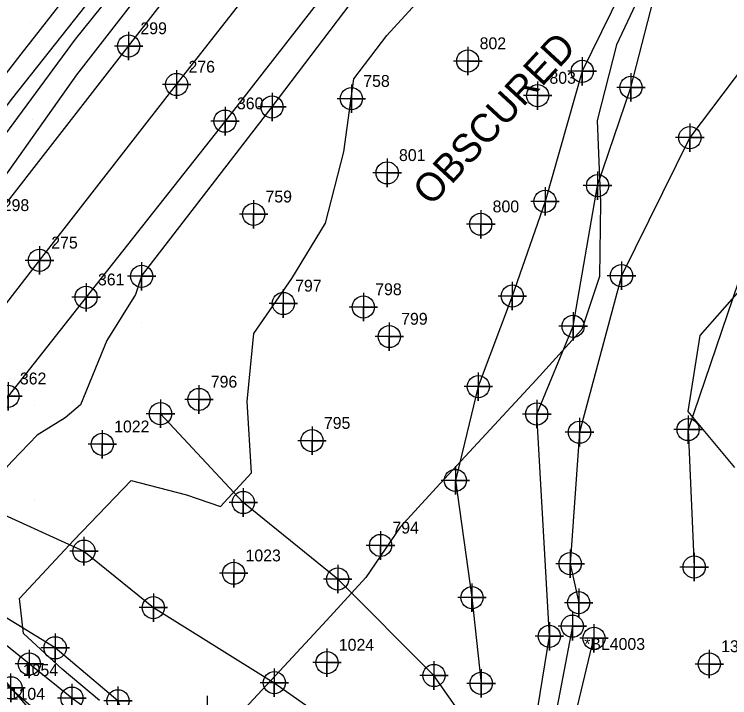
# Model space of a CAD drawing. Extents: x 1497074 to 1501343, y 481943 to 486114.
# Drawn here: x 1498779.1 to 1498929.9, y 484965.4 to 485109.5 of the extents above; entities that cross this region are included whole.
import ezdxf

# ---------------------------------------------------------------- set-up
doc = ezdxf.new("R2010")
doc.units = 0
for name, color, linetype in [('Exist DTM Breakline', 7, 'Continuous'), ('Exist DTM Breakline Cogo Point CELL', 7, 'Continuous'), ('Exist DTM Breakline Underwater Cogo Number', 7, 'Continuous'), ('Exist DTM Crownline', 7, 'Continuous'), ('Exist DTM Crownline Cogo Number', 7, 'Continuous'), ('Exist DTM Crownline Cogo Point CELL', 7, 'Continuous'), ('Exist DTM Drainline', 7, 'Continuous'), ('Exist DTM Drainline Cogo Comment', 7, 'Continuous'), ('Exist DTM Drainline Cogo Point CELL', 7, 'Continuous'), ('Exist DTM Regular Point CELL', 7, 'Continuous'), ('Exist DTM Regular Point Cogo Number', 7, 'Continuous'), ('Exist Hydro Stream or Body of Water', 7, 'Continuous'), ('Exist Hydro Stream or Body of Water Cogo Number', 7, 'Continuous'), ('Exist Hydro Stream or Body of Water Cogo Point CELL', 7, 'Continuous'), ('Exist Roads EOP', 7, 'Continuous'), ('Exist Roads EOP Cogo Number', 7, 'Continuous'), ('Exist Roads EOP Cogo Point CELL', 7, 'Continuous'), ('PH Exist DTM Boundary', 7, 'Continuous'), ('PH Exist DTM Breakline', 7, 'Continuous'), ('PH Exist DTM Obscure Area', 7, 'Continuous'), ('PH Exist DTM Obscure Area Text', 7, 'Continuous'), ('PH Exist DTM Point', 7, 'Continuous')]:
    doc.layers.add(name, color=color, linetype=linetype)

msp = doc.modelspace()

# ---------------------------------------------------------------- linework, layer by layer
at = {"layer": 'Exist DTM Breakline'}
for points in [[(1498805.95, 485054.25), (1498833.45, 485089.98), (1498860.79, 485126.09), (1498887.46, 485159.9), (1498914.16, 485195.14), (1498935.01, 485223.58), (1498950.21, 485241.65)], [(1498963.58, 485154.61), (1498950.43, 485151.68), (1498933.68, 485147.06), (1498922.77, 485137.59), (1498906.95, 485114.19), (1498898.82, 485097.51), (1498890.98, 485070.05), (1498884.07, 485050.09), (1498876.91, 485030.97), (1498872.08, 485011.19)], [(1498891.9, 484978.31), (1498889.24, 485025.19), (1498896.9, 485043.7), (1498902.05, 485073.39), (1498909.09, 485094.11), (1498914.43, 485114.93), (1498921.86, 485126.97), (1498937, 485141.32), (1498954.93, 485147.67), (1498969.97, 485147.43)], [(1498999.68, 485104.8), (1498976.97, 485110), (1498959.54, 485112.86), (1498942.37, 485111.16), (1498921.51, 485083.5), (1498907.1, 485054.37), (1498898.24, 485021.36), (1498896.28, 484993.61), (1498898.08, 484985.39)], [(1498969.44, 485104.51), (1498948.52, 485082.03), (1498932.91, 485056.44), (1498921.14, 485021.92), (1498922.42, 484992.91)], [(1498886.17, 484945.87), (1498882.87, 484948.24), (1498867.57, 484970.04), (1498847.28, 484990.38), (1498827.38, 485006.53), (1498809.93, 485025.26)], [(1498872.08, 485011.19), (1498875.57, 484986.46), (1498877.52, 484968.37)], [(1498848.29, 484918.89), (1498845.04, 484921.7), (1498840.43, 484924.27), (1498836.93, 484932.71), (1498831.61, 484940.16), (1498825.71, 484945.62), (1498813.99, 484951.95), (1498810.05, 484953.43), (1498804.82, 484955.73), (1498800.95, 484964.7), (1498787.72, 484975.87), (1498775.66, 484983.28), (1498764.52, 484991.6), (1498761.62, 485000.66), (1498761.1, 485004.19), (1498764.01, 485009), (1498765.64, 485007.52), (1498768.65, 485008.02)], [(1498775.21, 485004.72), (1498793.79, 484996.26), (1498808.42, 484984.36), (1498833.91, 484968.52), (1498856.98, 484952.27), (1498870.26, 484939.1), (1498876.95, 484932.87)], [(1498800.01, 484958.89), (1498791.25, 484965.26), (1498782.28, 484972.47), (1498771.97, 484980.76)], [(1498890, 484942.31), (1498886.17, 484945.87), (1498887.51, 484951.1), (1498891.9, 484978.31)], [(1498890, 484942.31), (1498893.99, 484947.35), (1498901.29, 484977.88)]]:
    msp.add_lwpolyline(points, dxfattribs=at)
at = {"layer": 'Exist DTM Breakline Cogo Point CELL'}
for points in [[(1498898.82, 485100.51), (1498898.82, 485094.51), (1498898.82, 485097.51), (1498901.82, 485097.51), (1498895.82, 485097.51)], [(1498909.09, 485097.11), (1498909.09, 485091.11), (1498909.09, 485094.11), (1498912.09, 485094.11), (1498906.09, 485094.11)], [(1498833.45, 485092.98), (1498833.45, 485086.98), (1498833.45, 485089.98), (1498836.45, 485089.98), (1498830.45, 485089.98)], [(1498921.51, 485086.5), (1498921.51, 485080.5), (1498921.51, 485083.5), (1498924.51, 485083.5), (1498918.51, 485083.5)], [(1498902.05, 485076.39), (1498902.05, 485070.39), (1498902.05, 485073.39), (1498905.05, 485073.39), (1498899.05, 485073.39)], [(1498890.98, 485073.05), (1498890.98, 485067.05), (1498890.98, 485070.05), (1498893.98, 485070.05), (1498887.98, 485070.05)], [(1498805.95, 485057.25), (1498805.95, 485051.25), (1498805.95, 485054.25), (1498808.95, 485054.25), (1498802.95, 485054.25)], [(1498907.1, 485057.37), (1498907.1, 485051.37), (1498907.1, 485054.37), (1498910.1, 485054.37), (1498904.1, 485054.37)], [(1498884.07, 485053.09), (1498884.07, 485047.09), (1498884.07, 485050.09), (1498887.07, 485050.09), (1498881.07, 485050.09)], [(1498896.9, 485046.7), (1498896.9, 485040.7), (1498896.9, 485043.7), (1498899.9, 485043.7), (1498893.9, 485043.7)], [(1498876.91, 485033.97), (1498876.91, 485027.97), (1498876.91, 485030.97), (1498879.91, 485030.97), (1498873.91, 485030.97)], [(1498809.93, 485028.26), (1498809.93, 485022.26), (1498809.93, 485025.26), (1498812.93, 485025.26), (1498806.93, 485025.26)], [(1498889.24, 485028.19), (1498889.24, 485022.19), (1498889.24, 485025.19), (1498892.24, 485025.19), (1498886.24, 485025.19)], [(1498898.24, 485024.36), (1498898.24, 485018.36), (1498898.24, 485021.36), (1498901.24, 485021.36), (1498895.24, 485021.36)], [(1498921.14, 485024.92), (1498921.14, 485018.92), (1498921.14, 485021.92), (1498924.14, 485021.92), (1498918.14, 485021.92)], [(1498872.08, 485014.19), (1498872.08, 485008.19), (1498872.08, 485011.19), (1498875.08, 485011.19), (1498869.08, 485011.19)], [(1498827.38, 485009.53), (1498827.38, 485003.53), (1498827.38, 485006.53), (1498830.38, 485006.53), (1498824.38, 485006.53)], [(1498793.79, 484999.26), (1498793.79, 484993.26), (1498793.79, 484996.26), (1498796.79, 484996.26), (1498790.79, 484996.26)], [(1498896.28, 484996.61), (1498896.28, 484990.61), (1498896.28, 484993.61), (1498899.28, 484993.61), (1498893.28, 484993.61)], [(1498922.42, 484995.91), (1498922.42, 484989.91), (1498922.42, 484992.91), (1498925.42, 484992.91), (1498919.42, 484992.91)], [(1498847.28, 484993.38), (1498847.28, 484987.38), (1498847.28, 484990.38), (1498850.28, 484990.38), (1498844.28, 484990.38)], [(1498875.57, 484989.46), (1498875.57, 484983.46), (1498875.57, 484986.46), (1498878.57, 484986.46), (1498872.57, 484986.46)], [(1498808.42, 484987.36), (1498808.42, 484981.36), (1498808.42, 484984.36), (1498811.42, 484984.36), (1498805.42, 484984.36)], [(1498898.08, 484988.39), (1498898.08, 484982.39), (1498898.08, 484985.39), (1498901.08, 484985.39), (1498895.08, 484985.39)], [(1498891.9, 484981.31), (1498891.9, 484975.31), (1498891.9, 484978.31), (1498894.9, 484978.31), (1498888.9, 484978.31)], [(1498901.29, 484980.88), (1498901.29, 484974.88), (1498901.29, 484977.88), (1498904.29, 484977.88), (1498898.29, 484977.88)], [(1498787.72, 484978.87), (1498787.72, 484972.87), (1498787.72, 484975.87), (1498790.72, 484975.87), (1498784.72, 484975.87)], [(1498782.28, 484975.47), (1498782.28, 484969.47), (1498782.28, 484972.47), (1498785.28, 484972.47), (1498779.28, 484972.47)], [(1498867.57, 484973.04), (1498867.57, 484967.04), (1498867.57, 484970.04), (1498870.57, 484970.04), (1498864.57, 484970.04)], [(1498833.91, 484971.52), (1498833.91, 484965.52), (1498833.91, 484968.52), (1498836.91, 484968.52), (1498830.91, 484968.52)], [(1498877.52, 484971.37), (1498877.52, 484965.37), (1498877.52, 484968.37), (1498880.52, 484968.37), (1498874.52, 484968.37)], [(1498791.25, 484968.26), (1498791.25, 484962.26), (1498791.25, 484965.26), (1498794.25, 484965.26), (1498788.25, 484965.26)], [(1498800.95, 484967.7), (1498800.95, 484961.7), (1498800.95, 484964.7), (1498803.95, 484964.7), (1498797.95, 484964.7)], [(1498819.73, 484965.72), (1498819.73, 484959.72), (1498819.73, 484962.72), (1498822.73, 484962.72), (1498816.73, 484962.72)]]:
    msp.add_lwpolyline(points, dxfattribs=at)
for centre in [(1498898.82, 485097.51), (1498909.09, 485094.11), (1498833.45, 485089.98), (1498921.51, 485083.5), (1498902.05, 485073.39), (1498890.98, 485070.05), (1498907.1, 485054.37), (1498805.95, 485054.25), (1498884.07, 485050.09), (1498896.9, 485043.7), (1498876.91, 485030.97), (1498809.93, 485025.26), (1498889.24, 485025.19), (1498898.24, 485021.36), (1498921.14, 485021.92), (1498872.08, 485011.19), (1498827.38, 485006.53), (1498793.79, 484996.26), (1498896.28, 484993.61), (1498922.42, 484992.91), (1498847.28, 484990.38), (1498875.57, 484986.46), (1498898.08, 484985.39), (1498808.42, 484984.36), (1498891.9, 484978.31), (1498901.29, 484977.88), (1498787.72, 484975.87), (1498782.28, 484972.47), (1498867.57, 484970.04), (1498833.91, 484968.52), (1498877.52, 484968.37), (1498791.25, 484965.26), (1498800.95, 484964.7)]:
    msp.add_circle(centre, 2.34, dxfattribs=at)
at = {"layer": 'Exist DTM Crownline'}
msp.add_lwpolyline([(1498753.92, 485018.83), (1498767.97, 485036.35), (1498784.41, 485057.61), (1498813.33, 485094.71), (1498845.11, 485135.39), (1498876.05, 485175.22), (1498907.7, 485215.72), (1498939.87, 485257.15), (1498970.73, 485296.32), (1499001.6, 485335.5), (1499032.55, 485374.36), (1499053.88, 485400.5), (1499073.91, 485423.48), (1499090.49, 485441.64), (1499112.37, 485464.57), (1499148.43, 485501.47), (1499184.54, 485537.77), (1499215.93, 485569.25), (1499248.51, 485602.52), (1499285.02, 485638.96), (1499320.99, 485674.8), (1499344.91, 485698.57), (1499374.04, 485727.35), (1499398.21, 485750.96)], dxfattribs=at)
at = {"layer": 'Exist DTM Crownline Cogo Point CELL'}
for points in [[(1498813.33, 485097.71), (1498813.33, 485091.71), (1498813.33, 485094.71), (1498816.33, 485094.71), (1498810.33, 485094.71)], [(1498784.41, 485060.61), (1498784.41, 485054.61), (1498784.41, 485057.61), (1498787.41, 485057.61), (1498781.41, 485057.61)]]:
    msp.add_lwpolyline(points, dxfattribs=at)
for centre in [(1498813.33, 485094.71), (1498784.41, 485057.61)]:
    msp.add_circle(centre, 2.34, dxfattribs=at)
at = {"layer": 'Exist DTM Drainline'}
msp.add_lwpolyline([(1498896.74, 484980.44), (1498890.78, 484949.15), (1498888.83, 484945.44)], dxfattribs=at)
at = {"layer": 'Exist DTM Drainline Cogo Point CELL'}
msp.add_lwpolyline([(1498896.74, 484983.44), (1498896.74, 484977.44), (1498896.74, 484980.44), (1498899.74, 484980.44), (1498893.74, 484980.44)], dxfattribs=at)
msp.add_circle((1498896.74, 484980.44), 2.34, dxfattribs=at)
at = {"layer": 'Exist DTM Regular Point CELL'}
for points in [[(1498874.7, 485102.66), (1498874.7, 485096.66), (1498874.7, 485099.66), (1498877.7, 485099.66), (1498871.7, 485099.66)], [(1498850.17, 485094.71), (1498850.17, 485088.71), (1498850.17, 485091.71), (1498853.17, 485091.71), (1498847.17, 485091.71)], [(1498889.41, 485095.37), (1498889.41, 485089.37), (1498889.41, 485092.37), (1498892.41, 485092.37), (1498886.41, 485092.37)], [(1498857.7, 485079.07), (1498857.7, 485073.07), (1498857.7, 485076.07), (1498860.7, 485076.07), (1498854.7, 485076.07)], [(1498829.56, 485070.33), (1498829.56, 485064.33), (1498829.56, 485067.33), (1498832.56, 485067.33), (1498826.56, 485067.33)], [(1498877.44, 485068.24), (1498877.44, 485062.24), (1498877.44, 485065.24), (1498880.44, 485065.24), (1498874.44, 485065.24)], [(1498835.81, 485051.52), (1498835.81, 485045.52), (1498835.81, 485048.52), (1498838.81, 485048.52), (1498832.81, 485048.52)], [(1498852.69, 485050.77), (1498852.69, 485044.77), (1498852.69, 485047.77), (1498855.69, 485047.77), (1498849.69, 485047.77)], [(1498858.16, 485044.54), (1498858.16, 485038.54), (1498858.16, 485041.54), (1498861.16, 485041.54), (1498855.16, 485041.54)], [(1498818.03, 485031.27), (1498818.03, 485025.27), (1498818.03, 485028.27), (1498821.03, 485028.27), (1498815.03, 485028.27)], [(1498841.87, 485022.57), (1498841.87, 485016.57), (1498841.87, 485019.57), (1498844.87, 485019.57), (1498838.87, 485019.57)], [(1498797.66, 485021.81), (1498797.66, 485015.81), (1498797.66, 485018.81), (1498800.66, 485018.81), (1498794.66, 485018.81)], [(1498856.31, 485000.47), (1498856.31, 484994.47), (1498856.31, 484997.47), (1498859.31, 484997.47), (1498853.31, 484997.47)], [(1498825.36, 484994.61), (1498825.36, 484988.61), (1498825.36, 484991.61), (1498828.36, 484991.61), (1498822.36, 484991.61)], [(1498845.02, 484975.75), (1498845.02, 484969.75), (1498845.02, 484972.75), (1498848.02, 484972.75), (1498842.02, 484972.75)], [(1498925.6, 484975.46), (1498925.6, 484969.46), (1498925.6, 484972.46), (1498928.6, 484972.46), (1498922.6, 484972.46)]]:
    msp.add_lwpolyline(points, dxfattribs=at)
for centre in [(1498874.7, 485099.66), (1498889.41, 485092.37), (1498850.17, 485091.71), (1498857.7, 485076.07), (1498829.56, 485067.33), (1498877.44, 485065.24), (1498835.81, 485048.52), (1498852.69, 485047.77), (1498858.16, 485041.54), (1498818.03, 485028.27), (1498797.66, 485018.81), (1498841.87, 485019.57), (1498856.31, 484997.47), (1498825.36, 484991.61), (1498845.02, 484972.75), (1498925.6, 484972.46)]:
    msp.add_circle(centre, 2.34, dxfattribs=at)
at = {"layer": 'Exist Hydro Stream or Body of Water'}
msp.add_lwpolyline([(1498752.44, 484994.87), (1498757.91, 484987.33), (1498768.39, 484979.37), (1498778.41, 484967.43), (1498786.59, 484957.96), (1498794.74, 484956.31), (1498800.32, 484956.39), (1498808.7, 484950.71), (1498819.06, 484944.96), (1498828.44, 484936.12), (1498833.88, 484929.92), (1498837.65, 484922.31), (1498844.31, 484916.7), (1498846.68, 484914.59)], dxfattribs=at)
at = {"layer": 'Exist Hydro Stream or Body of Water Cogo Point CELL'}
msp.add_lwpolyline([(1498775.41, 484967.43), (1498781.41, 484967.43), (1498778.41, 484967.43), (1498778.41, 484964.43), (1498778.41, 484970.43)], dxfattribs=at)
msp.add_circle((1498778.41, 484967.43), 2.34, dxfattribs=at)
at = {"layer": 'Exist Roads EOP'}
for points in [[(1498744.68, 485026.11), (1498757.92, 485043.98), (1498774.18, 485065.51), (1498803.2, 485102.82), (1498835.11, 485143.9), (1498866.39, 485184.06), (1498897.92, 485224.48), (1498930.45, 485265.81), (1498960.65, 485304.75), (1498991.78, 485343.69), (1499023.06, 485383.27), (1499044.83, 485409.1), (1499064.02, 485432.02), (1499081.8, 485451.06), (1499098.44, 485468.79), (1499108.29, 485478.99), (1499123.4, 485494.87), (1499138.72, 485510.78), (1499164.22, 485538.41), (1499168.24, 485544.59), (1499172.31, 485548.88)], [(1499157.4, 485492.59), (1499121.26, 485455.44), (1499103.51, 485436.37), (1499090.83, 485422.86), (1499076.19, 485406.52), (1499058.81, 485386.53), (1499043.51, 485368.33), (1499011.4, 485327.87), (1498980.6, 485289.07), (1498949.57, 485249.28), (1498917.76, 485208.17), (1498886.39, 485167.84), (1498854.95, 485127.37), (1498823.54, 485086.98), (1498794.25, 485049.83), (1498777.79, 485028.94), (1498763.43, 485011.14)]]:
    msp.add_lwpolyline(points, dxfattribs=at)
at = {"layer": 'Exist Roads EOP Cogo Point CELL'}
for points in [[(1498803.2, 485105.82), (1498803.2, 485099.82), (1498803.2, 485102.82), (1498806.2, 485102.82), (1498800.2, 485102.82)], [(1498823.54, 485089.98), (1498823.54, 485083.98), (1498823.54, 485086.98), (1498826.54, 485086.98), (1498820.54, 485086.98)], [(1498794.25, 485052.83), (1498794.25, 485046.83), (1498794.25, 485049.83), (1498797.25, 485049.83), (1498791.25, 485049.83)], [(1498777.79, 485031.94), (1498777.79, 485025.94), (1498777.79, 485028.94), (1498780.79, 485028.94), (1498774.79, 485028.94)]]:
    msp.add_lwpolyline(points, dxfattribs=at)
for centre in [(1498803.2, 485102.82), (1498823.54, 485086.98), (1498794.25, 485049.83), (1498777.79, 485028.94)]:
    msp.add_circle(centre, 2.34, dxfattribs=at)
at = {"layer": 'PH Exist DTM Boundary'}
for points in [[(1498924.23, 484841.06), (1498545.19, 485168.9), (1498846.5, 485569.16), (1499227.59, 485244.03)], [(1498186.43, 484771.69), (1498560.82, 484438.23), (1498782.89, 484653.31), (1498924.23, 484841.06), (1498545.19, 485168.9), (1498406.94, 484985.26)]]:
    msp.add_lwpolyline(points, close=True, dxfattribs=at)
at = {"layer": 'PH Exist DTM Breakline'}
for points in [[(1498734.08, 485041.24), (1498754.74, 485067.73), (1498780.54, 485101.09), (1498824.31, 485157.07), (1498837.32, 485174.23), (1498853.51, 485188.89), (1498855.22, 485191.48), (1498859.56, 485202.36), (1498862.65, 485206.71), (1498881.54, 485231.44), (1498927.36, 485290.03), (1498951.79, 485321.5), (1498962.84, 485336.05), (1498979.43, 485356.32), (1498990.51, 485369.6), (1499009.18, 485392.86), (1499024.73, 485411.52), (1499033.33, 485421.86)], [(1499036.52, 485418.7), (1499027.32, 485407.39), (1499017.38, 485396.35), (1499002.31, 485377.51), (1498977.67, 485347.09), (1498957.72, 485322.22), (1498937.17, 485295.29), (1498914.54, 485266.95), (1498888.36, 485232.91), (1498866.74, 485204.81), (1498863.23, 485199.86), (1498859.45, 485189.95), (1498858.07, 485187.01), (1498856.34, 485185.13), (1498845.15, 485175.65), (1498841.76, 485172.64), (1498838.03, 485168.05), (1498822.45, 485147.26), (1498778.76, 485091.87), (1498751.41, 485056.08), (1498737.86, 485038.39)], [(1498972.3, 485322.66), (1498970.18, 485324.47), (1498967.17, 485325.17), (1498965.07, 485323.79), (1498949.79, 485304.69), (1498935.28, 485286.87), (1498915.35, 485261.2), (1498891.02, 485231.12), (1498874.53, 485208.66), (1498866.26, 485195.19), (1498863.48, 485189.54), (1498859.9, 485185.08), (1498855.01, 485179.8), (1498847.87, 485173.62), (1498837.45, 485161.58), (1498823.24, 485143.14), (1498791.92, 485104.25), (1498766.81, 485070.17), (1498751.51, 485051.48), (1498741.16, 485039.07)], [(1498967.58, 485319.5), (1498953.54, 485301.18), (1498940.24, 485285), (1498924.19, 485265.02), (1498898.72, 485232.52), (1498877.54, 485205.03), (1498865.81, 485188.77), (1498860.37, 485181.15), (1498847.43, 485166.28), (1498828.35, 485142.72), (1498816.12, 485127.57), (1498792.19, 485096.75), (1498777.96, 485076.54), (1498762.02, 485055.04), (1498749.3, 485039.82), (1498744.94, 485035.76), (1498740.95, 485034.05), (1498738.24, 485032.84)], [(1498805.95, 485054.25), (1498804.69, 485050.38), (1498798.61, 485040.73), (1498793.07, 485027.16), (1498789.8, 485024.41), (1498783.95, 485020.73), (1498778.69, 485015.23), (1498774.74, 485010.96), (1498770.87, 485003.27)]]:
    msp.add_lwpolyline(points, dxfattribs=at)
at = {"layer": 'PH Exist DTM Obscure Area'}
for points in [[(1498797.07, 484964.73), (1498789.18, 484971.37), (1498781.05, 484978.89), (1498780.23, 484986.26), (1498791.65, 484998.61), (1498803.78, 485011.14), (1498815.38, 485008.12), (1498822.6, 485005.69), (1498829.08, 485012.82), (1498828.2, 485027.87), (1498829.62, 485042.21), (1498837.63, 485053.8), (1498844.69, 485065.46), (1498848.55, 485080.53), (1498850.66, 485095.9), (1498857.67, 485105.02), (1498865.29, 485113.46), (1498873.53, 485124.7), (1498876.87, 485142.66), (1498886.64, 485153.46), (1498910.14, 485178.87), (1498929.86, 485200.31), (1498949.24, 485225.58)], [(1498932.39, 485176.27), (1498927.4, 485162.25), (1498926.46, 485149.23), (1498925.77, 485138.8), (1498922.43, 485127.6), (1498912.38, 485116.58), (1498906.06, 485103.06), (1498901.97, 485087.14), (1498902.67, 485069.84), (1498902.48, 485054.19), (1498898.76, 485043.05), (1498889.14, 485032.4), (1498879.45, 485021.92), (1498868.06, 485009.61), (1498860.43, 485001.36), (1498853.22, 484990.68), (1498844.89, 484981.67), (1498835.97, 484972.02), (1498827.65, 484963.02)], [(1498931, 485013.9), (1498921.16, 485025.74), (1498923.66, 485041.76), (1498932.55, 485051.81)]]:
    msp.add_lwpolyline(points, dxfattribs=at)
at = {"layer": 'PH Exist DTM Point'}
for p, q in [((1498782.45, 485107.86), (1498782.45, 485107.86)), ((1498803.32, 485107.05), (1498803.32, 485107.05)), ((1498783, 485087.35), (1498783, 485087.35)), ((1498805.97, 485044.6), (1498805.97, 485044.6)), ((1498783.29, 485027.06), (1498783.29, 485027.06)), ((1498783.3, 485007.07), (1498783.3, 485007.07)), ((1498865.37, 485005.16), (1498865.37, 485005.16))]:
    msp.add_line(p, q, dxfattribs=at)

# ---------------------------------------------------------------- texts
at = {"layer": 'Exist DTM Breakline Underwater Cogo Number'}
msp.add_text('1104', height=2.5, dxfattribs=at).set_placement((1498778.15, 484964.92))
at = {"layer": 'Exist DTM Crownline Cogo Number'}
for s, p in [('276', (1498815.83, 485097.21)), ('275', (1498786.91, 485060.11))]:
    msp.add_text(s, height=2.5, dxfattribs=at).set_placement(p)
at = {"layer": 'Exist DTM Drainline Cogo Comment'}
msp.add_text('*BL4003', height=2.5, dxfattribs=at).set_placement((1498899.24, 484975.44))
at = {"layer": 'Exist DTM Regular Point Cogo Number'}
for s, p in [('802', (1498877.2, 485102.16)), ('803', (1498891.91, 485094.87)), ('758', (1498852.67, 485094.21)), ('801', (1498860.2, 485078.57)), ('759', (1498832.06, 485069.83)), ('800', (1498879.94, 485067.74)), ('797', (1498838.31, 485051.02)), ('798', (1498855.19, 485050.27)), ('799', (1498860.66, 485044.04)), ('796', (1498820.53, 485030.77)), ('1022', (1498800.16, 485021.32)), ('795', (1498844.37, 485022.07)), ('794', (1498858.81, 484999.97)), ('1023', (1498827.86, 484994.11)), ('1024', (1498847.52, 484975.26)), ('1376', (1498928.1, 484974.96))]:
    msp.add_text(s, height=2.5, dxfattribs=at).set_placement(p)
at = {"layer": 'Exist Hydro Stream or Body of Water Cogo Number'}
msp.add_text('1054', height=2.5, dxfattribs=at).set_placement((1498780.91, 484969.93))
at = {"layer": 'Exist Roads EOP Cogo Number'}
for s, p in [('299', (1498805.7, 485105.33)), ('360', (1498826.04, 485089.48)), ('298', (1498776.68, 485068.01)), ('361', (1498796.75, 485052.33)), ('362', (1498780.29, 485031.44))]:
    msp.add_text(s, height=2.5, dxfattribs=at).set_placement(p)
at = {"layer": 'PH Exist DTM Obscure Area Text'}
msp.add_text('OBSCURED', height=6, rotation=47.2398, dxfattribs=at).set_placement((1498866.98, 485068.86))

doc.saveas('drawing.dxf')
